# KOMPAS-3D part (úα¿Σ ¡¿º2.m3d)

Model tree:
1. Эскиз:1
2. Операция выдавливания:1
     Расстояние 1 = 108
3. Скругление:1
     Радиус = 11
4. Скругление:2
     Радиус = 11
5. Эскиз:2
6. Операция выдавливания:2
     Расстояние 1 = 108; Расстояние 2 = 17
7. Эскиз:3
8. Вырезать элемент выдавливания:1
     Расстояние 1 = 120
9. Скругление:3
     Радиус = 11
10. Скругление:4
     Радиус = 11
